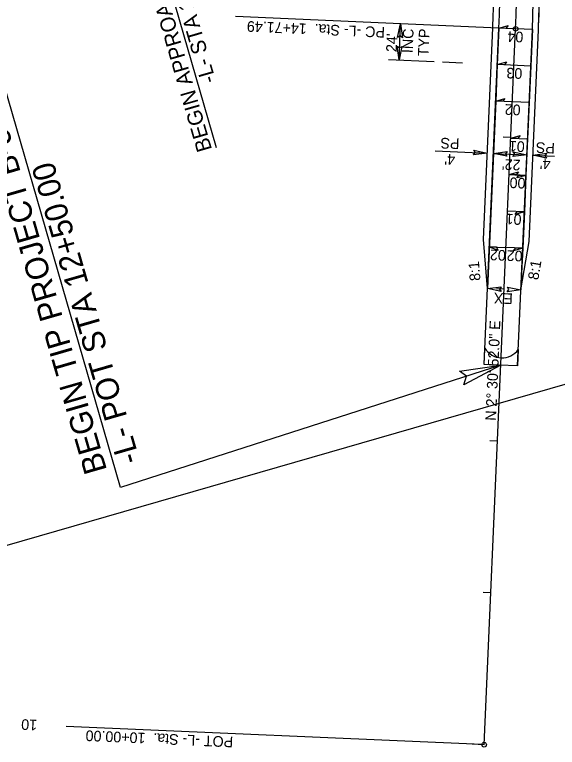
# Model space of a CAD drawing. Extents: x 2167182 to 2168576, y 842635 to 844493.
# Drawn here: x 2167753.4 to 2168110, y 842635.3 to 843117.4 of the extents above; entities that cross this region are included whole.
import ezdxf

# ---------------------------------------------------------------- set-up
doc = ezdxf.new("R2010")
doc.units = 0
for name, color, linetype in [('Default', 7, 'Continuous'), ('Old_Level_2', 7, 'Continuous'), ('Old_Level_63', 7, 'Continuous'), ('Prop Dimension', 7, 'Continuous'), ('Prop Dimension Text', 7, 'Continuous'), ('Prop EOT', 7, 'Continuous'), ('Prop Horizontal Alignment', 7, 'Continuous'), ('Prop Horizontal Alignment Direction Label', 7, 'Continuous'), ('Prop Horizontal Alignment Station Label', 7, 'Continuous'), ('Prop Horizontal Alignment Tick Label', 7, 'Continuous'), ('Prop Horizontal Alignment Tick Large', 7, 'Continuous'), ('Prop Horizontal Alignment Tick Small', 7, 'Continuous'), ('Prop Paved Shoulder', 7, 'Continuous'), ('Prop Shade Light', 7, 'Continuous'), ('Prop Superelevation  Arrow CELL', 7, 'Continuous'), ('Prop Superelevation Label', 7, 'Continuous'), ('Prop Terminator CELL', 7, 'Continuous'), ('Sheet Layout Plan Border', 7, 'Continuous')]:
    doc.layers.add(name, color=color, linetype=linetype)

msp = doc.modelspace()

# ---------------------------------------------------------------- linework, layer by layer
at = {"layer": 'Default'}
msp.add_line((2168084.39, 842897.11), (2168083.92, 842886.33), dxfattribs=at)
for points in [[(2168061.94, 842887.29), (2168062.41, 842898.08), (2168062.41, 842898.08)], [(2168083.92, 842886.33), (2168071.85, 842886.86), (2168061.94, 842887.29)]]:
    msp.add_lwpolyline(points, dxfattribs=at)
msp.add_arc((2168073.71, 842904.62), 13.05, 210.0698, 324.9013, dxfattribs=at)
at = {"layer": 'Old_Level_63'}
for points in [[(2168073.06, 842935.3), (2168064.13, 842937.24), (2168073.24, 842938.45), (2168072.02, 842936.9)], [(2168077.19, 842938.22), (2168086.11, 842936.28), (2168077, 842935.08), (2168078.22, 842936.63)]]:
    msp.add_lwpolyline(points, close=True, dxfattribs=at)
at = {"layer": 'Prop Dimension'}
for p, q in [((2168005.99, 843087.64), (2168007.04, 843111.41)), ((2167999.08, 843087.97), (2168029.06, 843086.57)), ((2168034.68, 843086.3), (2168047.61, 843085.7)), ((2168029.65, 843027.85), (2168064.04, 843026.34)), ((2168068.04, 843026.17), (2168090.02, 843025.2)), ((2168094.01, 843025.03), (2168108.23, 843024.4))]:
    msp.add_line(p, q, dxfattribs=at)
for points in [[(2167886.12, 843029.83), (2167840.2, 843188.68), (2168002.9, 843301.76)], [(2168072.93, 842886.81), (2167822.86, 842806.27), (2167740.86, 843090.03)]]:
    msp.add_lwpolyline(points, dxfattribs=at)
at = {"layer": 'Prop EOT'}
for p, q in [((2168061.94, 842887.29), (2168071.66, 843108.57)), ((2168083.92, 842886.33), (2168093.63, 843107.6))]:
    msp.add_line(p, q, dxfattribs=at)
for radius in [822, 844]:
    msp.add_arc((2167250.45, 843144.63), radius, 357.48556, 7.27898, dxfattribs=at)
at = {"layer": 'Prop Horizontal Alignment'}
msp.add_line((2168061.96, 842637.05), (2168082.64, 843108.09), dxfattribs=at)
msp.add_arc((2167250.45, 843144.63), 833, 357.48556, 7.27898, dxfattribs=at)
at = {"layer": 'Prop Horizontal Alignment Station Label'}
for p, q in [((2168081.15, 843108.15), (2167898.62, 843116.17)), ((2168060.46, 842637.12), (2167787.22, 842649.11))]:
    msp.add_line(p, q, dxfattribs=at)
for centre in [(2168082.64, 843108.09), (2168061.96, 842637.05)]:
    msp.add_circle(centre, 1.5, dxfattribs=at)
at = {"layer": 'Prop Horizontal Alignment Tick Large'}
msp.add_line((2168061.96, 842637.05), (2168053.97, 842637.4), dxfattribs=at)
at = {"layer": 'Prop Horizontal Alignment Tick Small'}
for p, q in [((2168079.51, 843036.66), (2168074.51, 843036.88)), ((2168075.12, 842936.76), (2168070.13, 842936.98)), ((2168070.73, 842836.86), (2168065.74, 842837.08)), ((2168066.35, 842736.95), (2168061.35, 842737.17))]:
    msp.add_line(p, q, dxfattribs=at)
at = {"layer": 'Prop Paved Shoulder'}
for p, q in [((2168061.54, 842969.39), (2168067.66, 843108.74)), ((2168091.51, 842968.07), (2168097.63, 843107.43)), ((2168064.13, 842937.24), (2168061.54, 842969.39)), ((2168086.11, 842936.28), (2168091.51, 842968.07))]:
    msp.add_line(p, q, dxfattribs=at)
for radius, end in [(818, 6.52426), (848, 1)]:
    msp.add_arc((2167250.45, 843144.63), radius, 357.48556, end, dxfattribs=at)
at = {"layer": 'Prop Shade Light'}
for p, q in [((2168061.54, 842969.39), (2168067.66, 843108.74)), ((2168091.51, 842968.07), (2168097.63, 843107.43)), ((2168064.13, 842937.24), (2168061.54, 842969.39)), ((2168086.11, 842936.28), (2168091.51, 842968.07)), ((2168086.59, 842947.23), (2168086.11, 842936.28))]:
    msp.add_line(p, q, dxfattribs=at)
for points in [[(2168071.66, 843108.57), (2168070.6, 843084.59), (2168069.55, 843060.61), (2168064.13, 842937.24)], [(2168093.63, 843107.6), (2168092.58, 843083.63), (2168091.53, 843059.65), (2168090.48, 843035.67), (2168089.42, 843011.7), (2168088.37, 842987.72), (2168087.32, 842963.74), (2168086.59, 842947.23)]]:
    msp.add_lwpolyline(points, dxfattribs=at)
for radius, end in [(848, 7.27898), (822, 7.27898), (844, 7.27898), (818, 6.52426)]:
    msp.add_arc((2167250.45, 843144.63), radius, 357.48556, end, dxfattribs=at)
at = {"layer": 'Prop Superelevation  Arrow CELL'}
for p, q in [((2168093.63, 843107.6), (2168071.66, 843108.57)), ((2168092.58, 843083.63), (2168070.6, 843084.59)), ((2168091.53, 843059.65), (2168069.55, 843060.61)), ((2168079.49, 843036.16), (2168090.48, 843035.67)), ((2168078.43, 843012.18), (2168089.42, 843011.7)), ((2168089.42, 843011.7), (2168078.43, 843012.18)), ((2168088.37, 842987.72), (2168077.38, 842988.2)), ((2168065.34, 842964.71), (2168076.33, 842964.22)), ((2168087.32, 842963.74), (2168076.33, 842964.22))]:
    msp.add_line(p, q, dxfattribs=at)
for points in [[(2168071.66, 843108.57), (2168077.74, 843110.3), (2168076.28, 843108.37)], [(2168070.6, 843084.59), (2168076.68, 843086.33), (2168075.22, 843084.39)], [(2168069.55, 843060.61), (2168075.63, 843062.35), (2168074.17, 843060.41)], [(2168079.49, 843036.16), (2168085.57, 843037.89), (2168084.11, 843035.95)], [(2168078.43, 843012.18), (2168084.52, 843013.91), (2168083.05, 843011.98)], [(2168089.42, 843011.7), (2168083.34, 843009.96), (2168084.8, 843011.9)], [(2168088.37, 842987.72), (2168082.29, 842985.98), (2168083.75, 842987.92)], [(2168065.34, 842964.71), (2168071.24, 842962.45), (2168069.96, 842964.5)], [(2168087.32, 842963.74), (2168081.23, 842962.01), (2168082.7, 842963.95)]]:
    msp.add_lwpolyline(points, close=True, dxfattribs=at)
at = {"layer": 'Prop Terminator CELL'}
for points in [[(2168005.09, 843102.48), (2168007.04, 843111.41), (2168008.24, 843102.29), (2168006.69, 843103.51)], [(2168007.94, 843096.57), (2168005.99, 843087.64), (2168004.79, 843096.76), (2168006.34, 843095.54)], [(2168055.12, 843028.29), (2168064.04, 843026.34), (2168054.93, 843025.14), (2168056.15, 843026.69)], [(2168076.96, 843024.23), (2168068.04, 843026.17), (2168077.15, 843027.37), (2168075.93, 843025.82)], [(2168081.09, 843027.15), (2168090.02, 843025.2), (2168080.9, 843024), (2168082.12, 843025.55)], [(2168102.94, 843023.08), (2168094.01, 843025.03), (2168103.12, 843026.23), (2168101.9, 843024.68)], [(2168045.8, 842882.96), (2168072.93, 842886.81), (2168048.56, 842873.92), (2168050.37, 842879.55)]]:
    msp.add_lwpolyline(points, close=True, dxfattribs=at)
at = {"layer": 'Sheet Layout Plan Border'}
msp.add_lwpolyline([(2168191.21, 844341.01), (2167182.42, 844049.75), (2167182.42, 844049.75), (2167567.43, 842716.21), (2168576.23, 843007.46)], close=True, dxfattribs=at)

# ---------------------------------------------------------------- texts
at = {"layer": 'Old_Level_2'}
for s, height, p in [('BEGIN APPROACH SLAB', 10, (2167883.17, 843028.8)), ('-L- STA 17+09.15', 10, (2167885.76, 843073.83)), ('BEGIN TIP PROJECT B-5325', 15, (2167814.18, 842817.73)), ('-L- POT STA 12+50.00', 15, (2167835.8, 842823.98))]:
    msp.add_text(s, height=height, rotation=106.1263, dxfattribs=at).set_placement(p)
at = {"layer": 'Old_Level_63'}
msp.add_text('EX', height=7, rotation=177.4856, dxfattribs=at).set_placement((2168080.96, 842933.94))
at = {"layer": 'Prop Dimension Text'}
for s, rotation, p in [('INC', 87.4856, (2168014.94, 843092.02)), ('TYP', 87.4856, (2168025.35, 843089.89)), ("24'", 87.4856, (2168004.45, 843092.68)), ('PS', 177.4856, (2168045.88, 843035.92)), ('PS', 177.4856, (2168108.6, 843033)), ("4'", 177.4856, (2168042.99, 843025.53)), ("22'", 177.4856, (2168086, 843021.88)), ("4'", 177.4856, (2168105.71, 843022.62)), ('8:1', 94.6106, (2168059.55, 842942.51)), ('8:1', 80.3605, (2168097.51, 842942.51))]:
    msp.add_text(s, height=7, rotation=rotation, dxfattribs=at).set_placement(p)
at = {"layer": 'Prop Horizontal Alignment Direction Label'}
msp.add_text('N 2%%d 30\' 52.0" E', height=7, rotation=87.4856, dxfattribs=at).set_placement((2168069.74, 842850.12))
at = {"layer": 'Prop Horizontal Alignment Station Label'}
for s, p in [('PC -L- Sta.  14+71.49', (2167996.91, 843109.26)), ('POT -L- Sta.  10+00.00', (2167897.13, 842642.29))]:
    msp.add_text(s, height=7, rotation=177.4856, dxfattribs=at).set_placement(p)
at = {"layer": 'Prop Horizontal Alignment Tick Label'}
msp.add_text('10', height=7, rotation=177.4856, dxfattribs=at).set_placement((2167768.26, 842653.45))
at = {"layer": 'Prop Superelevation Label'}
for s, p in [('04', (2168087.85, 843106.11)), ('03', (2168087.16, 843082.11)), ('02', (2168086.05, 843058.14)), ('01', (2168088.76, 843034)), ('00', (2168089.25, 843009.95)), ('01', (2168086.65, 842986.04)), ('02', (2168076.34, 842962.47)), ('02', (2168087.33, 842961.99))]:
    msp.add_text(s, height=7, rotation=177.4856, dxfattribs=at).set_placement(p)

doc.saveas('drawing.dxf')
